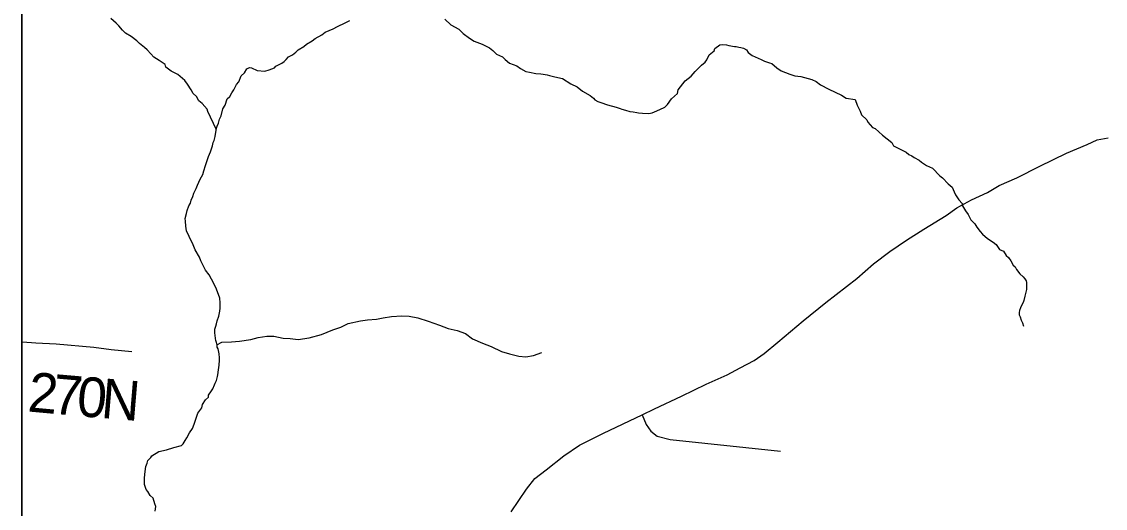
# Model space of a CAD drawing. Extents: x 0 to 39.3, y -3.9 to 22.
# Drawn here: x 1.9 to 3.453, y 14.794 to 15.491 of the extents above; entities that cross this region are included whole.
import ezdxf

# ---------------------------------------------------------------- set-up
doc = ezdxf.new("R2010")
doc.units = 0
for name, color, linetype in [('GM_X_Corporation', 7, 'Continuous'), ('GM_X_Minor_River', 7, 'Continuous'), ('GM_X_State_Route', 7, 'Continuous'), ('GM_X_Township_Road', 7, 'Continuous'), ('GM_X_Township_Road_Text', 7, 'Continuous'), ('SH_Data', 7, 'Continuous')]:
    doc.layers.add(name, color=color, linetype=linetype)

msp = doc.modelspace()

# ---------------------------------------------------------------- linework, layer by layer
at = {"layer": 'GM_X_Corporation'}
msp.add_lwpolyline([(3.5402, 15.8703), (2.8431, 15.7483), (2.8288, 15.7458), (2.6537, 15.7535), (2.5893, 15.7591), (2.5183, 15.7585), (2.4514, 15.75), (2.406, 15.7581), (2.3534, 15.7684), (2.3314, 15.7727), (2.2384, 15.7885), (2.1447, 15.8042), (2.054, 15.8197), (1.9627, 15.8365), (1.9, 15.8496), (1.9, 13.9), (3.8692, 13.9)], dxfattribs=at)
at = {"layer": 'GM_X_Minor_River'}
for points in [[(2.1788, 15.3371), (2.1667, 15.3625), (2.1656, 15.3659), (2.1585, 15.3741), (2.154, 15.3779), (2.1507, 15.3841), (2.1458, 15.3884), (2.1429, 15.3934), (2.1377, 15.4018), (2.1336, 15.4072), (2.1239, 15.4154), (2.1144, 15.4205), (2.1065, 15.4263), (2.1055, 15.4298), (2.0972, 15.4356), (2.0893, 15.4403), (2.0852, 15.445), (2.0796, 15.4508), (2.0758, 15.4543), (2.0687, 15.4601), (2.065, 15.464), (2.0571, 15.4702), (2.0488, 15.4749), (2.0447, 15.4792), (2.0391, 15.4854), (2.0353, 15.4892), (2.0279, 15.4958)], [(2.3164, 15.4637), (2.3207, 15.4671), (2.3299, 15.4726), (2.3349, 15.476), (2.3464, 15.4811), (2.3526, 15.4844), (2.3637, 15.4895), (2.3703, 15.4929)], [(2.5062, 15.4947), (2.5148, 15.4866), (2.5265, 15.4803), (2.5325, 15.4745), (2.5415, 15.4675), (2.5483, 15.4635), (2.56, 15.4588), (2.5702, 15.454), (2.575, 15.4498), (2.5806, 15.4447), (2.589, 15.4408), (2.5927, 15.4369), (2.5991, 15.4318), (2.6093, 15.4279), (2.6149, 15.424), (2.6225, 15.42), (2.6278, 15.4188), (2.6365, 15.4171), (2.6437, 15.4166), (2.6471, 15.4162), (2.6528, 15.4153), (2.6562, 15.4141), (2.6638, 15.4121), (2.6748, 15.41), (2.6868, 15.4022), (2.6959, 15.3978), (2.7034, 15.3916), (2.7147, 15.3857), (2.7196, 15.3818), (2.7211, 15.3791), (2.7256, 15.3771), (2.7298, 15.3755), (2.7392, 15.3723), (2.7517, 15.3687), (2.7574, 15.3671), (2.76, 15.3659), (2.7653, 15.3647), (2.7714, 15.3626), (2.776, 15.3622), (2.7813, 15.361), (2.7839, 15.3605), (2.7896, 15.36), (2.7988, 15.3599), (2.8033, 15.3606), (2.8068, 15.362), (2.8145, 15.3653), (2.8218, 15.3686), (2.8256, 15.3728), (2.8311, 15.3807), (2.8396, 15.3885), (2.8409, 15.3934), (2.8506, 15.4066), (2.8591, 15.4133), (2.8649, 15.4197), (2.8684, 15.4234), (2.8742, 15.429), (2.8793, 15.4331), (2.8816, 15.4365), (2.8852, 15.4437), (2.8925, 15.4493), (2.8933, 15.4527), (2.9006, 15.4579), (2.9048, 15.4586), (2.9098, 15.4581), (2.9132, 15.4573), (2.9212, 15.4556), (2.9238, 15.4556), (2.9276, 15.4547), (2.9307, 15.4543), (2.9344, 15.4531), (2.9386, 15.4508), (2.9412, 15.4473), (2.9468, 15.4426)], [(2.1675, 14.9535), (2.1679, 14.9562), (2.1718, 14.9626), (2.1738, 14.9656), (2.1762, 14.9709), (2.1774, 14.9735), (2.179, 14.9773), (2.1806, 14.983), (2.181, 14.9856), (2.1815, 14.9887), (2.1819, 14.9929), (2.1823, 14.9955), (2.1828, 14.9997), (2.1833, 15.0062), (2.1834, 15.01), (2.1831, 15.0153), (2.1827, 15.018), (2.1817, 15.0226), (2.1802, 15.0252), (2.1799, 15.0279), (2.1792, 15.0317), (2.1781, 15.0348), (2.1778, 15.0375), (2.1771, 15.0424), (2.1768, 15.0451), (2.1769, 15.0508), (2.1781, 15.055), (2.1793, 15.0584), (2.1801, 15.0626), (2.1825, 15.0697), (2.1838, 15.0766), (2.1843, 15.0808), (2.1844, 15.0884), (2.1838, 15.0952), (2.1794, 15.1079), (2.1754, 15.1163), (2.1688, 15.1286), (2.1632, 15.1352), (2.1606, 15.1409), (2.1569, 15.1486), (2.1548, 15.154), (2.1485, 15.1644), (2.1456, 15.1716), (2.1401, 15.1835), (2.136, 15.1916), (2.135, 15.1985), (2.1347, 15.2053), (2.1344, 15.2095), (2.1361, 15.2167), (2.1369, 15.2209), (2.1393, 15.2277), (2.1417, 15.2315), (2.1429, 15.2356), (2.1453, 15.2409), (2.1469, 15.2455), (2.1501, 15.2523), (2.1521, 15.2572), (2.156, 15.2659), (2.1596, 15.2723), (2.1612, 15.2776), (2.1632, 15.2851), (2.1648, 15.2897), (2.1676, 15.298), (2.1708, 15.3048), (2.1736, 15.3135), (2.1745, 15.3181), (2.1757, 15.3211), (2.1773, 15.3268), (2.179, 15.3389), (2.1802, 15.3416), (2.1818, 15.3457), (2.1835, 15.3518), (2.1858, 15.3563), (2.1883, 15.3662), (2.1918, 15.3715), (2.1946, 15.3805), (2.1981, 15.3839), (2.2009, 15.3892), (2.204, 15.3937), (2.208, 15.4012), (2.2111, 15.405), (2.2146, 15.4137), (2.2193, 15.4178), (2.2224, 15.4235), (2.2263, 15.4257), (2.2293, 15.4252), (2.2372, 15.4213), (2.2483, 15.4203), (2.2548, 15.4225), (2.2621, 15.4251), (2.2644, 15.4277), (2.2728, 15.4317), (2.2759, 15.4343), (2.279, 15.437), (2.2825, 15.4407), (2.2879, 15.4436), (2.2929, 15.4477), (2.2964, 15.4507), (2.3041, 15.4556), (2.308, 15.4589), (2.3164, 15.4637)], [(2.9468, 15.4426), (2.9596, 15.4371), (2.9646, 15.4347), (2.9717, 15.4323), (2.9748, 15.4315), (2.9823, 15.4249), (2.9883, 15.4206), (3.0008, 15.4162), (3.008, 15.4138), (3.0163, 15.4125), (3.0322, 15.4084), (3.0386, 15.4056), (3.0446, 15.4006), (3.0567, 15.3947), (3.0748, 15.386), (3.0812, 15.3817), (3.0941, 15.3799), (3.0974, 15.3715), (3.1014, 15.3631), (3.1032, 15.3577), (3.1111, 15.3507), (3.1126, 15.3473), (3.1193, 15.3395), (3.1231, 15.3383), (3.1336, 15.3286), (3.1467, 15.3181), (3.1493, 15.3135), (3.1557, 15.31), (3.1674, 15.3045), (3.1711, 15.301), (3.1753, 15.299), (3.1787, 15.2967), (3.1858, 15.2931), (3.1892, 15.29), (3.1967, 15.2853), (3.205, 15.2814), (3.2155, 15.2705), (3.2196, 15.2674), (3.2278, 15.2589), (3.2331, 15.2542), (3.2364, 15.2473), (3.2382, 15.2431), (3.243, 15.2362), (3.2475, 15.2308), (3.2482, 15.2277), (3.2523, 15.2204), (3.256, 15.215), (3.26, 15.2073), (3.2656, 15.2019), (3.2686, 15.1969), (3.2734, 15.1907), (3.2768, 15.1869), (3.2839, 15.1807), (3.2922, 15.1756), (3.2963, 15.1721), (3.3011, 15.1651), (3.3068, 15.1624), (3.3105, 15.1562), (3.3142, 15.1535), (3.3176, 15.1489), (3.3209, 15.1423), (3.3235, 15.14), (3.3253, 15.1362), (3.3302, 15.13), (3.3351, 15.1257), (3.3373, 15.123), (3.3391, 15.1203), (3.3399, 15.1176), (3.3397, 15.1078), (3.3389, 15.104), (3.3376, 15.0983), (3.336, 15.0918), (3.3348, 15.0888), (3.3324, 15.0839), (3.3312, 15.0813), (3.33, 15.0778), (3.3292, 15.0748), (3.3295, 15.0714), (3.3306, 15.0687), (3.332, 15.0637), (3.3342, 15.0599), (3.3355, 15.0551)], [(2.1798, 15.0286), (2.1866, 15.0322), (2.2006, 15.0326), (2.2121, 15.0335), (2.2284, 15.0362), (2.2391, 15.039), (2.2513, 15.0406), (2.2612, 15.0408), (2.2748, 15.0378), (2.2846, 15.0373), (2.2964, 15.0362), (2.312, 15.0382), (2.3296, 15.0431), (2.3457, 15.05), (2.3571, 15.0539), (2.3679, 15.059), (2.3854, 15.0628), (2.3953, 15.0641), (2.4083, 15.0653), (2.4182, 15.067), (2.43, 15.069), (2.4448, 15.0699), (2.455, 15.0693), (2.4675, 15.0671), (2.4826, 15.0622), (2.4988, 15.0565), (2.5112, 15.0517), (2.524, 15.0491), (2.5361, 15.0447), (2.5462, 15.0372), (2.5601, 15.0309), (2.5729, 15.026), (2.5875, 15.0189), (2.5988, 15.0156), (2.6124, 15.0122), (2.6226, 15.0112), (2.6333, 15.0129), (2.6455, 15.0172)], [(2.0911, 14.79), (2.0923, 14.7968), (2.0909, 14.8007), (2.0884, 14.8087), (2.0842, 14.8126), (2.0809, 14.8184), (2.0783, 14.8214), (2.0769, 14.8253), (2.0758, 14.8283), (2.0759, 14.8371), (2.0764, 14.8432), (2.0781, 14.8542), (2.0798, 14.8587), (2.081, 14.8629), (2.0852, 14.867), (2.0864, 14.8696), (2.0964, 14.8756), (2.1075, 14.878), (2.1178, 14.8813), (2.1289, 14.8841), (2.1316, 14.8868), (2.1344, 14.8913), (2.1367, 14.895), (2.1403, 14.9022), (2.145, 14.9086), (2.147, 14.915), (2.1506, 14.9249), (2.1526, 14.9306), (2.1581, 14.9381), (2.1589, 14.943), (2.1636, 14.9494), (2.1675, 14.9535)]]:
    msp.add_lwpolyline(points, dxfattribs=at)
at = {"layer": 'GM_X_State_Route'}
msp.add_lwpolyline([(2.6014, 14.7891), (2.6233, 14.8215), (2.6353, 14.8369), (2.6517, 14.8494), (2.6769, 14.8693), (2.6993, 14.8849), (2.7338, 14.9017), (2.789, 14.9283), (2.8066, 14.9369), (2.8457, 14.9551), (2.8808, 14.9719), (2.9107, 14.9856), (2.9294, 14.9956), (2.9497, 15.0062), (2.9638, 15.0161), (2.9837, 15.0323), (3.0197, 15.0627), (3.0522, 15.089), (3.0967, 15.1232), (3.1204, 15.1446), (3.144, 15.1622), (3.1677, 15.1785), (3.1928, 15.1943), (3.2245, 15.2135), (3.2402, 15.2246), (3.261, 15.236), (3.2838, 15.2465), (3.3006, 15.2566), (3.3259, 15.2677), (3.3591, 15.2844), (3.3972, 15.3029), (3.4268, 15.3151), (3.4411, 15.3218), (3.4568, 15.325)], dxfattribs=at)
at = {"layer": 'GM_X_Township_Road'}
for points in [[(1.9, 15.0327), (1.9014, 15.0325), (1.9201, 15.0315)], [(1.9201, 15.0315), (1.9494, 15.0299), (2.0032, 15.0249), (2.0283, 15.0219), (2.058, 15.0188)], [(2.789, 14.9283), (2.7947, 14.9145), (2.8017, 14.9049), (2.8106, 14.8977), (2.829, 14.8926), (2.9871, 14.8759)]]:
    msp.add_lwpolyline(points, dxfattribs=at)
at = {"layer": 'SH_Data'}
msp.add_lwpolyline([(1.9, 21.1), (9.1, 21.1), (9.1, 13.9), (1.9, 13.9)], close=True, dxfattribs=at)

# ---------------------------------------------------------------- texts
at = {"layer": 'GM_X_Township_Road_Text'}
for s, rotation, p in [('2', 354.7967, (1.9075, 14.9331)), ('7', 355.0609, (1.9426, 14.9299)), ('0', 355.1481, (1.9776, 14.9268)), ('N', 355.1733, (2.0125, 14.9239))]:
    msp.add_text(s, height=0.0568, rotation=rotation, dxfattribs=at).set_placement(p)

doc.saveas('drawing.dxf')
